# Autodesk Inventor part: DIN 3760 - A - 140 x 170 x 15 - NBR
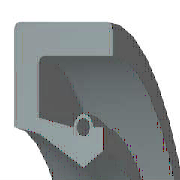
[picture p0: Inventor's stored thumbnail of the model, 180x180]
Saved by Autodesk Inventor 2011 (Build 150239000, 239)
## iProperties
IsCustomPart: 0
Created: 2010-02
Part Number: DIN 3760 - A - 140 x 170 x 15 - NBR
Material: Rubber
Description: Shaft Seal Ring
Document SubType Name: Modeling
Standard: DIN 3760
Designer: 129877
Standards Organization: DIN
Language: en-US
Size Designation: A - 140 x 170 x 15 - NBR
Categories: <MemberInstance><Categories><Category DisplayName="Shaft Parts" InternalName="7f7aeb1f-a693-4053-b835-cee3144e0d98" Mnemonic="SHFT"><Category DisplayName="Seali
Density: 0.93 g/cm^3
Mass: 51.5123 g
Surface Area: 366.495 cm^2
Volume: 55.3895 cm^3
Author: 129877
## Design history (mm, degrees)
revolve "Body" stored, may be unused: angle "d17" = 90 deg
revolve "Spring1" stored, may be unused: angle "d18" = 90 deg
body "Solid1"
sketch "Sketch1"
  geometry: L1 (0, 85)-(15, 85); L2 (15, 85)-(15, 81.75); L3 (15, 81.75)-(3.75, 81.75); L4 (0, 85)-(0, 74.5); L5 (0, 74.5)-(3.75, 73.75); L6 (3.75, 73.75)-(10.5, 70); L7 (10.5, 70)-(0, 70); L8 (13.5, 71.875)-(13.5, 74.5); L9 (0, 0)-(9.586, 0) reference; L10 (10.5, 70)-(13.5, 71.875); L11 (0, 18)-(0, -3) reference; L12 (-1.917, 0)-(11.503, 0) reference; L13 (9, 74.5)-(3.75, 75.55); L14 (3.75, 75.55)-(3.75, 81.75); L15 (13.5, 74.5)-(12, 74.5); C1 r 0.975 at (10.5, 74.5); A1 r 1.5 centre (10.5, 74.5) between (12, 74.5) and (9, 74.5)
  constraints: 26 end point, 5 horizontal alignment, 4 perpendicular, 2 centre point, 2 collinear, 2 horizontal, 2 parallel, 2 point on circle, 2 point on line, 2 vertical alignment, 1 coincident
  dimensions: "d0" = 170 diameter of L1 L9 (= SD2); "d1" = 143.75 diameter of L8.start L9 (= ABDM); "d2" = 3.25 distance of L1.end L2.end (computed from SD); "d3" = 1.95 diameter of C1 (= SPDI); "d4" = 3 diameter of A1 (= SPDA); "d5" = 140 diameter of L6.end L9 (= NND); "d6" = 147.5 diameter of L5.end L9 (= TKDM); "d7" = 149 diameter of L4.end L9 (= HLDM); "d8" = 10.5 distance from line of C1.centre L4 (= SPDST); "d9" = 13.5 distance between parallel lines of L8 L4 (= SDI); "d10" = 15 distance between parallel lines of L2 L4 (= SWDT); "d12" = 3.75 distance between parallel lines of L14 L4 (= SD)
fillet "Fillet1" dims "d11" = 1 (= RR)
other parameters: "SD2" = 170 [user parameter; used in 1 equation term], "SWDT" = 15 [user parameter; used in 1 equation term], "RR" = 1 [user parameter; used in 1 equation term], "SD" = 3.75 [user parameter; used in 2 equation terms], "NND" = 140 [user parameter; used in 1 equation term], "SPDA" = 3 [user parameter; used in 1 equation term], "SPDI" = 1.95 [user parameter; used in 1 equation term], "TKDM" = 147.5 [user parameter; used in 1 equation term], "HLDM" = 149 [user parameter; used in 1 equation term], "ABDM" = 143.75 [user parameter; used in 1 equation term], "SDI" = 13.5 [user parameter; used in 1 equation term], "SPDST" = 10.5 [user parameter; used in 1 equation term], "d13" = 0, "d14" = 0, "d15" = 0, "LAB" = 0.75 [user parameter]
